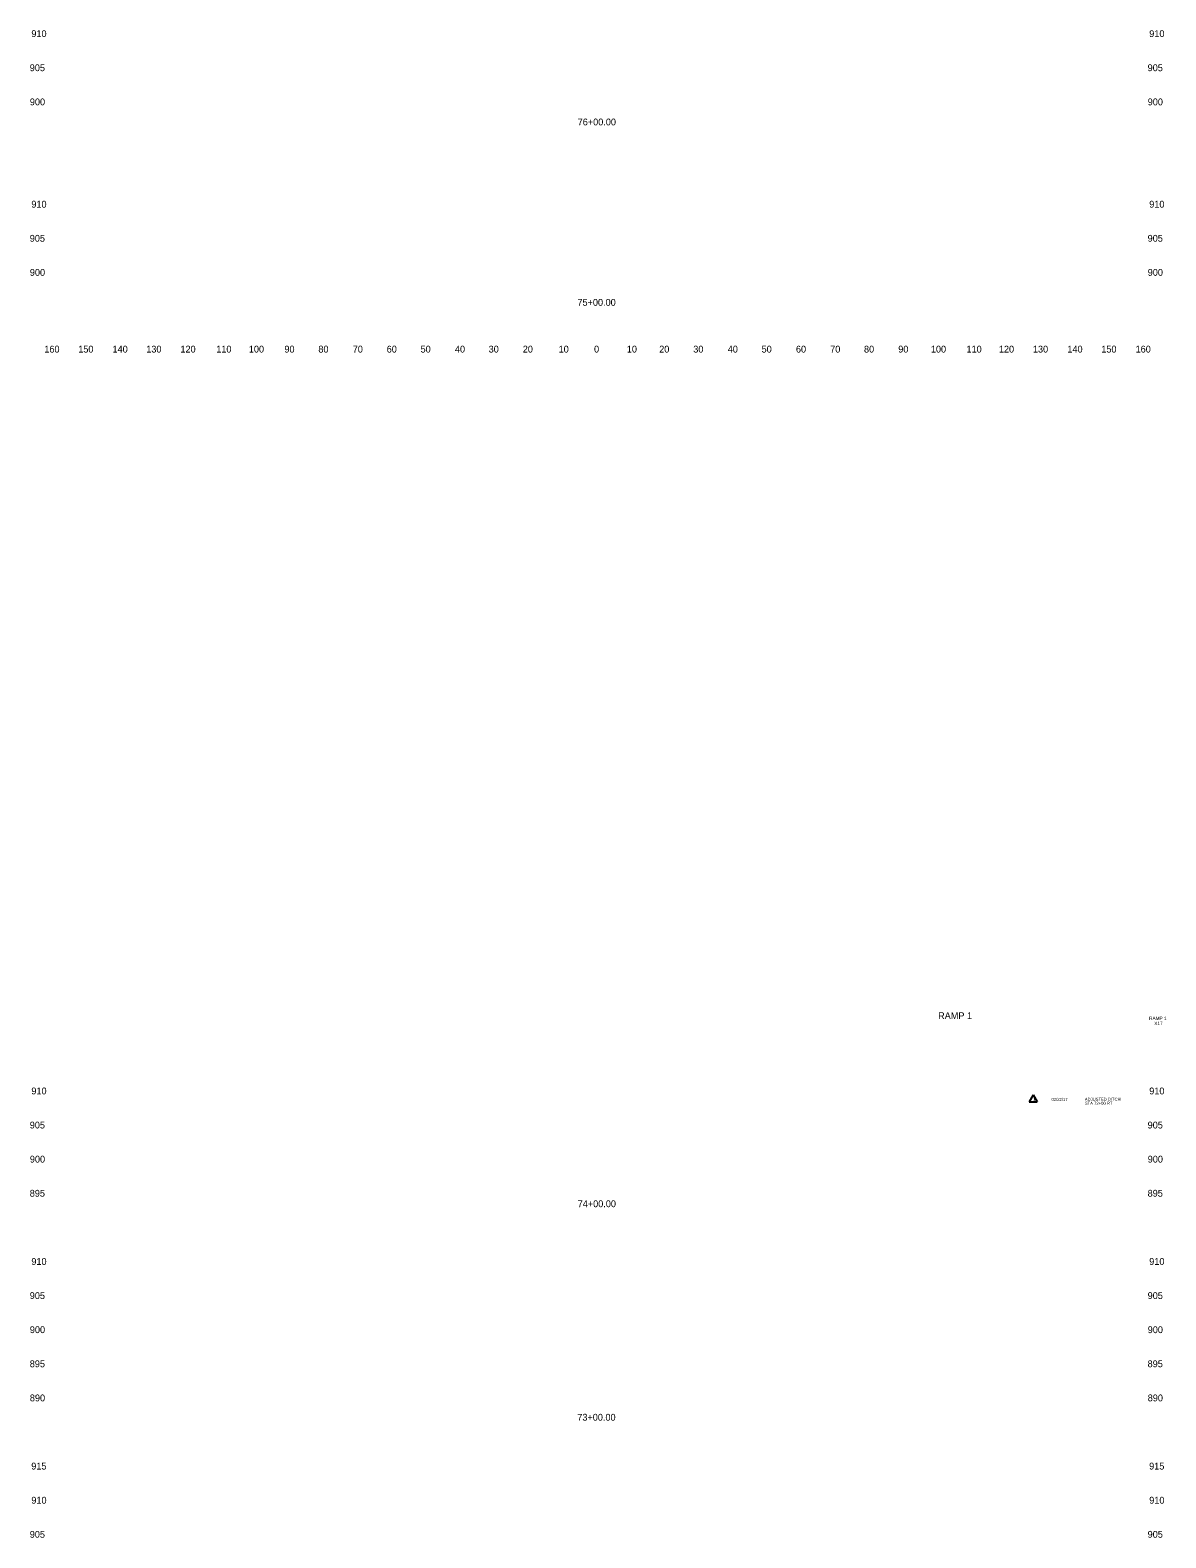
# Model space of a CAD drawing. Extents: x 4994 to 7869, y 4997 to 8804.
# Drawn here: x 5508.9 to 5842, y 7450 to 7892 of the extents above; entities that cross this region are included whole.
import ezdxf

# ---------------------------------------------------------------- set-up
doc = ezdxf.new("R2010")
doc.units = 0
for name, color, linetype in [('RD_SHT_ID', 7, 'Continuous'), ('RD_SHT_TX', 7, 'Continuous'), ('RD_XS_TX_Offset', 7, 'Continuous'), ('RD_XS_TX_Station', 7, 'Continuous')]:
    doc.layers.add(name, color=color, linetype=linetype)

msp = doc.modelspace()

# ---------------------------------------------------------------- linework, layer by layer
at = {"layer": 'RD_SHT_TX'}
for p, q in [((5803.05, 7579.83), (5801.91, 7577.8)), ((5801.91, 7577.8), (5804.19, 7577.8)), ((5803.05, 7579.83), (5804.19, 7577.8))]:
    msp.add_line(p, q, dxfattribs=at)

# ---------------------------------------------------------------- texts
at = {"layer": 'RD_SHT_ID'}
for s, height, p in [('RAMP 1', 2, (5775.19, 7602.06)), ('RAMP 1', 1, (5837.06, 7601.8)), ('X17', 1, (5838.57, 7600.3))]:
    msp.add_text(s, height=height, dxfattribs=at).set_placement(p)
at = {"layer": 'RD_SHT_TX'}
for s, p in [('1', (5803.05, 7578.13)), ('02/22/17', (5808.44, 7578.09)), ('ADJUSTED DITCH', (5818.22, 7578.12)), ('STA 72+00 RT', (5818.22, 7576.95))]:
    msp.add_text(s, height=0.88, dxfattribs=at).set_placement(p)
at = {"layer": 'RD_XS_TX_Offset'}
for s, p in [('910', (5509.3, 7890)), ('910', (5837.1, 7890)), ('905', (5508.83, 7880)), ('905', (5836.63, 7880)), ('900', (5508.86, 7870)), ('900', (5836.66, 7870)), ('910', (5509.3, 7840)), ('910', (5837.1, 7840)), ('905', (5508.83, 7830)), ('905', (5836.63, 7830)), ('900', (5508.86, 7820)), ('900', (5836.66, 7820)), ('160', (5513.1, 7797.5)), ('150', (5523.04, 7797.5)), ('140', (5533.1, 7797.5)), ('130', (5542.99, 7797.5)), ('120', (5553.01, 7797.5)), ('110', (5563.51, 7797.5)), ('100', (5573.07, 7797.5)), ('90', (5583.5, 7797.5)), ('80', (5593.46, 7797.5)), ('70', (5603.54, 7797.5)), ('60', (5613.5, 7797.5)), ('50', (5623.43, 7797.5)), ('40', (5633.5, 7797.5)), ('30', (5643.39, 7797.5)), ('20', (5653.4, 7797.5)), ('10', (5663.91, 7797.5)), ('0', (5674.3, 7797.5)), ('0', (5674.3, 7797.5)), ('10', (5683.91, 7797.5)), ('20', (5693.4, 7797.5)), ('30', (5703.39, 7797.5)), ('40', (5713.5, 7797.5)), ('50', (5723.43, 7797.5)), ('60', (5733.5, 7797.5)), ('70', (5743.54, 7797.5)), ('80', (5753.46, 7797.5)), ('90', (5763.5, 7797.5)), ('100', (5773.07, 7797.5)), ('110', (5783.51, 7797.5)), ('120', (5793.01, 7797.5)), ('130', (5802.99, 7797.5)), ('140', (5813.1, 7797.5)), ('150', (5823.04, 7797.5)), ('160', (5833.1, 7797.5)), ('910', (5509.3, 7580)), ('910', (5837.1, 7580)), ('905', (5508.83, 7570)), ('905', (5836.63, 7570)), ('900', (5508.86, 7560)), ('900', (5836.66, 7560)), ('895', (5508.83, 7550)), ('895', (5836.63, 7550)), ('910', (5509.3, 7530)), ('910', (5837.1, 7530)), ('905', (5508.83, 7520)), ('905', (5836.63, 7520)), ('900', (5508.86, 7510)), ('900', (5836.66, 7510)), ('895', (5508.83, 7500)), ('895', (5836.63, 7500)), ('890', (5508.86, 7490)), ('890', (5836.66, 7490)), ('915', (5509.27, 7470)), ('915', (5837.07, 7470)), ('910', (5509.3, 7460)), ('910', (5837.1, 7460)), ('905', (5508.83, 7450)), ('905', (5836.63, 7450))]:
    msp.add_text(s, height=2, dxfattribs=at).set_placement(p)
at = {"layer": 'RD_XS_TX_Station'}
for s, p in [('76+00.00', (5669.5, 7864.11)), ('75+00.00', (5669.43, 7811.22)), ('74+00.00', (5669.5, 7546.92)), ('73+00.00', (5669.39, 7484.33))]:
    msp.add_text(s, height=2, dxfattribs=at).set_placement(p)

doc.saveas('drawing.dxf')
